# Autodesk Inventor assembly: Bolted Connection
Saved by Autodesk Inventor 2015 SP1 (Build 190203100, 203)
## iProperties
Created: 2011-06
Part Number: Bolted Connection
Document SubType Name: Assembly
Designer: Guilherme Augusto Franco de Souza
ClientObjectVersion: 1
Author: Guilherme Augusto Franco de Souza
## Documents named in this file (4)
- E:\Visitor Experience Project\WSI2015 - Visitor Experience Project\#46- Sheet Metal Technology\01- 3D Models\Outodoor Heater\2- Assemblies\Outdoor Heater\Design Accelerator\Bolted Connection1.iam
- C:\Users\Guilherme Augusto\Documents\Inventor\Content Center Files\R2015\en-US\ISO 7089\ISO 7089 - 6 - 140 HV(1).ipt
- C:\Users\Guilherme Augusto\Documents\Inventor\Content Center Files\R2015\en-US\ISO 4017(1)\ISO 4017 - M6 x 40ISO.ipt
- C:\Users\Guilherme Augusto\Documents\Inventor\Content Center Files\R2015\en-US\ISO 4032(2)\ISO 4032 - M6ISO.ipt
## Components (16 placed, 3 different names)
1. ISO 7089 6 - 140 HV:9
2. ISO 4017 M6 x 40:5
3. ISO 7089 6 - 140 HV:10
4. ISO 4032 M6:5
5. ISO 4017 M6 x 40:2
6. ISO 4017 M6 x 40:3
7. ISO 4017 M6 x 40:4
8. ISO 7089 6 - 140 HV:3
9. ISO 7089 6 - 140 HV:4
10. ISO 7089 6 - 140 HV:5
11. ISO 7089 6 - 140 HV:6
12. ISO 7089 6 - 140 HV:7
13. ISO 7089 6 - 140 HV:8
14. ISO 4032 M6:2
15. ISO 4032 M6:3
16. ISO 4032 M6:4
